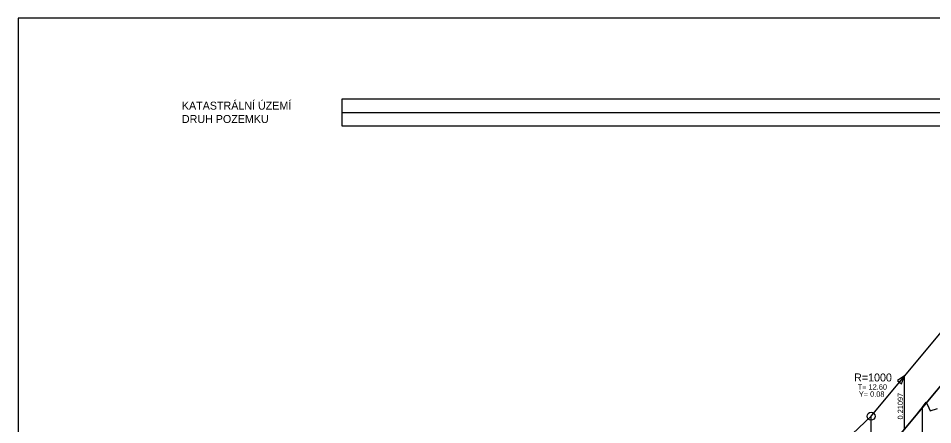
# Model space of a CAD drawing. Extents: x 1290 to 1438, y 129 to 174.
# Drawn here: x 1290.28 to 1324.57, y 158.67 to 173.92 of the extents above; entities that cross this region are included whole.
import ezdxf

# ---------------------------------------------------------------- set-up
doc = ezdxf.new("R2010")
doc.units = 0
for name, color, linetype in [('NOVY_STAV', 7, 'Continuous'), ('NS_OBLOUK', 7, 'Continuous'), ('REZY_PO', 7, 'Continuous'), ('SVK_STAT', 7, 'Continuous'), ('TABULKY', 7, 'Continuous'), ('x_formát_rám', 7, 'Continuous')]:
    doc.layers.add(name, color=color, linetype=linetype)

msp = doc.modelspace()

# ---------------------------------------------------------------- linework, layer by layer
at = {"layer": 'NOVY_STAV'}
for points in [[(1322.254, 158.988), (1332.417, 171.186)], [(1302.417, 147.214), (1313.777, 148.949), (1322.254, 156.988), (1332.417, 169.186)], [(1302.417, 147.214), (1311.39, 148.584), (1311.824, 148.666), (1312.258, 148.78), (1312.692, 148.924), (1313.126, 149.101), (1313.56, 149.308), (1313.994, 149.547), (1314.428, 149.817), (1314.862, 150.119), (1315.296, 150.452), (1315.73, 150.816), (1316.164, 151.212), (1320.994, 155.793), (1321.414, 156.2), (1321.834, 156.625), (1322.254, 157.067), (1322.674, 157.527), (1323.094, 158.004), (1323.514, 158.5), (1331.777, 168.418), (1332.179, 168.89), (1332.417, 169.158)], [(1313.777, 150.949), (1322.254, 158.988)], [(1322.254, 156.988), (1322.254, 158.988)]]:
    msp.add_lwpolyline(points, dxfattribs=at)
msp.add_circle((1322.254, 158.988), 0.15, dxfattribs=at)
at = {"layer": 'NS_OBLOUK'}
for points in [[(1323.398, 160.205), (1323.514, 160.5), (1323.245, 160.333), (1323.398, 160.205)], [(1323.514, 158.5), (1323.514, 160.5)]]:
    msp.add_lwpolyline(points, dxfattribs=at)
msp.add_lwpolyline([(1323.514, 160.5), (1323.245, 160.333), (1323.398, 160.205)], close=True, dxfattribs=at)
at = {"layer": 'REZY_PO'}
msp.add_lwpolyline([(1323.595, 158.601), (1323.774, 158.816), (1323.952, 159.037), (1324.13, 159.265), (1324.156, 159.298), (1324.182, 159.332), (1324.322, 159.514), (1324.417, 159.301), (1324.467, 159.188), (1324.75, 159.278)], dxfattribs=at)
at = {"layer": 'SVK_STAT'}
msp.add_lwpolyline([(1324.182, 140.194), (1324.182, 159.332)], dxfattribs=at)
at = {"layer": 'TABULKY'}
for points in [[(1302.417, 169.89), (1410.009, 169.89), (1410.009, 170.89), (1302.417, 170.89), (1302.417, 169.89)], [(1302.417, 170.39), (1410.009, 170.39)]]:
    msp.add_lwpolyline(points, dxfattribs=at)
at = {"layer": 'x_formát_rám'}
msp.add_lwpolyline([(1290.283, 129.368), (1437.283, 129.368), (1437.283, 173.918), (1290.283, 173.918)], close=True, dxfattribs=at)

# ---------------------------------------------------------------- texts
at = {"layer": 'NS_OBLOUK'}
for s, height, p in [('R=1000', 0.3, (1321.619, 160.294)), ('T= 12.60', 0.2, (1321.754, 159.988)), ('Y= 0.08', 0.2, (1321.797, 159.722))]:
    msp.add_text(s, height=height, dxfattribs=at).set_placement(p)
msp.add_text(' 0.21097', height=0.2, rotation=90, dxfattribs=at).set_placement((1323.452, 158.792))
at = {"layer": 'TABULKY'}
for s, p in [('KATASTRÁLNÍ ÚZEMÍ', (1296.417, 170.49)), ('DRUH POZEMKU', (1296.417, 169.99))]:
    msp.add_text(s, height=0.3, dxfattribs=at).set_placement(p)

doc.saveas('drawing.dxf')
